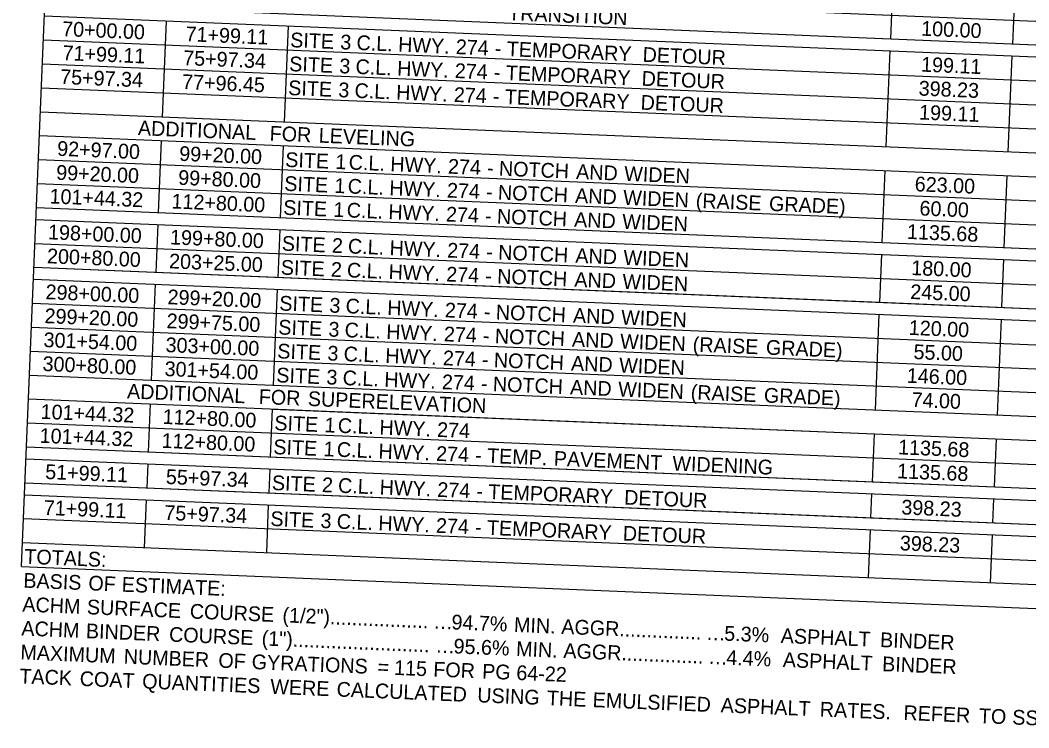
# Model space of a CAD drawing. Extents: x 1164179 to 1171425, y 1655958 to 1657208.
# Drawn here: x 1168003.6 to 1168414.3, y 1656231.5 to 1656519.5 of the extents above; entities that cross this region are included whole.
import ezdxf

# ---------------------------------------------------------------- set-up
doc = ezdxf.new("R2010")
doc.units = 0
doc.layers.add('Default', color=7, linetype='Continuous')

msp = doc.modelspace()

# ---------------------------------------------------------------- linework, layer by layer
at = {"layer": 'Default'}
for p, q in [((1168004.21, 1656297.14), (1168026.37, 1656832.93)), ((1168004.21, 1656297.14), (1168026.37, 1656832.93)), ((1168358.05, 1656511.82), (1168360.87, 1656580.01)), ((1168358.05, 1656511.82), (1168360.87, 1656580.01)), ((1168407.73, 1656509.76), (1168410.55, 1656577.96)), ((1168407.73, 1656509.76), (1168410.55, 1656577.96)), ((1168014.08, 1656535.81), (1169501.15, 1656474.29)), ((1168013.68, 1656526.07), (1168358.05, 1656511.82)), ((1168013.68, 1656526.07), (1169500.75, 1656464.55)), ((1168013.48, 1656521.19), (1169500.54, 1656459.68)), ((1168061.55, 1656480.17), (1168063.16, 1656519.14)), ((1168061.55, 1656480.17), (1168063.16, 1656519.14)), ((1168111.23, 1656478.12), (1168112.84, 1656517.08)), ((1168111.23, 1656478.12), (1168112.84, 1656517.08)), ((1168013.08, 1656511.45), (1169500.14, 1656449.94)), ((1168358.05, 1656511.82), (1169500.75, 1656464.55)), ((1168356.23, 1656467.98), (1168357.85, 1656506.95)), ((1168356.23, 1656467.98), (1168357.85, 1656506.95)), ((1168405.92, 1656465.93), (1168407.53, 1656504.89)), ((1168405.92, 1656465.93), (1168407.53, 1656504.89)), ((1168012.67, 1656501.71), (1169499.74, 1656440.19)), ((1168012.27, 1656491.97), (1169499.33, 1656430.45)), ((1168011.87, 1656482.23), (1168554.96, 1656459.76)), ((1168011.87, 1656482.23), (1169498.93, 1656420.71)), ((1168011.46, 1656472.49), (1169498.53, 1656410.97)), ((1168059.94, 1656441.21), (1168061.15, 1656470.43)), ((1168059.94, 1656441.21), (1168061.15, 1656470.43)), ((1168109.62, 1656439.15), (1168110.83, 1656468.38)), ((1168109.62, 1656439.15), (1168110.83, 1656468.38)), ((1168011.06, 1656462.74), (1169498.13, 1656401.23)), ((1168354.62, 1656429.02), (1168355.83, 1656458.24)), ((1168354.62, 1656429.02), (1168355.83, 1656458.24)), ((1168404.3, 1656426.96), (1168405.51, 1656456.18)), ((1168404.3, 1656426.96), (1168405.51, 1656456.18)), ((1168010.66, 1656453), (1169497.72, 1656391.49)), ((1168010.25, 1656443.26), (1168354.62, 1656429.02)), ((1168010.25, 1656443.26), (1169497.32, 1656381.74)), ((1168010.05, 1656438.39), (1169497.12, 1656376.87)), ((1168058.93, 1656416.85), (1168059.74, 1656436.33)), ((1168058.93, 1656416.85), (1168059.74, 1656436.33)), ((1168108.61, 1656414.8), (1168109.42, 1656434.28)), ((1168108.61, 1656414.8), (1168109.42, 1656434.28)), ((1168009.65, 1656428.65), (1169496.72, 1656367.13)), ((1168354.62, 1656429.02), (1169497.32, 1656381.74)), ((1168353.61, 1656404.66), (1168354.42, 1656424.14)), ((1168353.61, 1656404.66), (1168354.42, 1656424.14)), ((1168009.25, 1656418.91), (1168353.61, 1656404.66)), ((1168009.25, 1656418.91), (1169496.31, 1656357.39)), ((1168403.3, 1656402.61), (1168404.1, 1656422.09)), ((1168403.3, 1656402.61), (1168404.1, 1656422.09)), ((1168009.05, 1656414.04), (1169496.11, 1656352.52)), ((1168057.12, 1656373.01), (1168058.73, 1656411.98)), ((1168057.12, 1656373.01), (1168058.73, 1656411.98)), ((1168106.8, 1656370.96), (1168108.41, 1656409.93)), ((1168106.8, 1656370.96), (1168108.41, 1656409.93)), ((1168008.64, 1656404.29), (1169495.71, 1656342.78)), ((1168353.61, 1656404.66), (1169496.31, 1656357.39)), ((1168351.8, 1656360.82), (1168353.41, 1656399.79)), ((1168351.8, 1656360.82), (1168353.41, 1656399.79)), ((1168008.24, 1656394.55), (1169495.3, 1656333.04)), ((1168401.48, 1656358.77), (1168403.1, 1656397.73)), ((1168401.48, 1656358.77), (1168403.1, 1656397.73)), ((1168007.84, 1656384.81), (1169494.9, 1656323.29)), ((1168007.43, 1656375.07), (1169494.5, 1656313.55)), ((1168007.43, 1656375.07), (1169494.5, 1656313.55)), ((1168007.03, 1656365.33), (1169494.1, 1656303.81)), ((1168055.91, 1656343.79), (1168056.71, 1656363.27)), ((1168055.91, 1656343.79), (1168056.71, 1656363.27)), ((1168105.59, 1656341.73), (1168106.4, 1656361.22)), ((1168105.59, 1656341.73), (1168106.4, 1656361.22)), ((1168106.4, 1656361.22), (1168351.4, 1656351.08)), ((1168006.63, 1656355.59), (1169493.69, 1656294.07)), ((1168350.59, 1656331.6), (1168351.4, 1656351.08)), ((1168350.59, 1656331.6), (1168351.4, 1656351.08)), ((1168400.27, 1656329.54), (1168401.08, 1656349.03)), ((1168400.27, 1656329.54), (1168401.08, 1656349.03)), ((1168006.22, 1656345.84), (1168350.59, 1656331.6)), ((1168006.22, 1656345.84), (1169493.29, 1656284.33)), ((1168006.02, 1656340.97), (1169493.09, 1656279.46)), ((1168055.3, 1656329.18), (1168055.71, 1656338.92)), ((1168055.3, 1656329.18), (1168055.71, 1656338.92)), ((1168104.98, 1656327.12), (1168105.39, 1656336.86)), ((1168104.98, 1656327.12), (1168105.39, 1656336.86)), ((1168005.62, 1656331.23), (1168349.99, 1656316.99)), ((1168005.62, 1656331.23), (1169492.69, 1656269.71)), ((1168350.59, 1656331.6), (1169493.29, 1656284.33)), ((1168005.42, 1656326.36), (1169492.48, 1656264.84)), ((1168054.29, 1656304.82), (1168055.1, 1656324.31)), ((1168054.29, 1656304.82), (1168055.1, 1656324.31)), ((1168349.99, 1656316.99), (1168350.39, 1656326.73)), ((1168349.99, 1656316.99), (1168350.39, 1656326.73)), ((1168399.67, 1656314.93), (1168400.07, 1656324.67)), ((1168399.67, 1656314.93), (1168400.07, 1656324.67)), ((1168103.98, 1656302.77), (1168104.78, 1656322.25)), ((1168103.98, 1656302.77), (1168104.78, 1656322.25)), ((1168005.02, 1656316.62), (1169492.08, 1656255.1)), ((1168349.99, 1656316.99), (1169492.69, 1656269.71)), ((1168348.98, 1656292.63), (1168349.79, 1656312.12)), ((1168348.98, 1656292.63), (1168349.79, 1656312.12)), ((1168398.66, 1656290.58), (1168399.47, 1656310.06)), ((1168398.66, 1656290.58), (1168399.47, 1656310.06)), ((1168004.61, 1656306.88), (1169491.68, 1656245.36)), ((1168004.21, 1656297.14), (1169491.27, 1656235.62))]:
    msp.add_line(p, q, dxfattribs=at)

# ---------------------------------------------------------------- texts
for s, p in [(' TRANSITION', (1168200, 1656519.56)), ('70+00.00', (1168020.62, 1656513.02)), ('71+99.11', (1168070.87, 1656510.94)), ('100.00', (1168370.36, 1656513.19)), ('SITE', (1168113.46, 1656508.5)), (' 3', (1168131.64, 1656507.75)), (' C.L.', (1168138.24, 1656507.48)), ('71+99.11', (1168020.79, 1656503.25)), (' HWY.', (1168155.19, 1656506.77)), (' 274', (1168178.65, 1656505.8)), (' TEMPORARY', (1168199.39, 1656504.95)), ('75+97.34', (1168069.9, 1656501.22)), ('SITE', (1168113.06, 1656498.76)), (' -', (1168194.54, 1656505.15)), (' DETOUR', (1168254.72, 1656502.66)), (' 3', (1168131.23, 1656498.01)), (' C.L.', (1168137.84, 1656497.73)), (' HWY.', (1168154.79, 1656497.03)), (' 274', (1168178.25, 1656496.06)), (' TEMPORARY', (1168198.99, 1656495.2)), ('199.11', (1168370.33, 1656498.55)), ('75+97.34', (1168019.82, 1656493.53)), ('77+96.45', (1168069.46, 1656491.48)), (' -', (1168194.14, 1656495.41)), (' DETOUR', (1168254.32, 1656492.92)), ('SITE', (1168112.66, 1656489.02)), (' 3', (1168130.83, 1656488.27)), (' C.L.', (1168137.43, 1656487.99)), (' HWY.', (1168154.38, 1656487.29)), (' 274', (1168177.85, 1656486.32)), ('398.23', (1168369.35, 1656488.83)), (' -', (1168193.73, 1656485.66)), (' TEMPORARY', (1168198.59, 1656485.46)), (' DETOUR', (1168253.91, 1656483.17)), ('199.11', (1168369.52, 1656479.07)), ('ADDITIONAL', (1168051.48, 1656472.71)), (' FOR', (1168102.88, 1656470.58)), (' LEVELING', (1168122.85, 1656469.75)), ('92+97.00', (1168018.6, 1656464.31)), ('99+20.00', (1168068.29, 1656462.25)), ('SITE', (1168111.45, 1656459.79)), (' 1', (1168129.62, 1656459.04)), (' C.L.', (1168135.06, 1656458.82)), (' HWY.', (1168152.01, 1656458.11)), ('99+20.00', (1168018.2, 1656454.57)), (' 274', (1168175.48, 1656457.14)), (' NOTCH', (1168196.22, 1656456.29)), (' AND', (1168227.65, 1656454.99)), (' WIDEN', (1168247.22, 1656454.18)), ('99+80.00', (1168067.88, 1656452.51)), ('SITE', (1168111.05, 1656450.05)), (' -', (1168191.37, 1656456.49)), ('623.00', (1168367.74, 1656449.87)), (' 1', (1168129.22, 1656449.3)), (' C.L.', (1168134.66, 1656449.07)), (' HWY.', (1168151.61, 1656448.37)), (' 274', (1168175.07, 1656447.4)), (' NOTCH', (1168195.81, 1656446.54)), ('101+44.32', (1168015.49, 1656444.92)), ('112+80.00', (1168065.15, 1656442.87)), (' -', (1168190.96, 1656446.74)), (' AND', (1168227.25, 1656445.24)), (' WIDEN', (1168246.81, 1656444.43)), (' (RAISE', (1168276.37, 1656443.21)), (' GRADE)', (1168306.18, 1656441.98)), ('SITE', (1168110.64, 1656440.31)), (' 1', (1168128.81, 1656439.56)), (' C.L.', (1168134.26, 1656439.33)), (' HWY.', (1168151.21, 1656438.63)), (' 274', (1168174.67, 1656437.66)), ('60.00', (1168369.67, 1656440.03)), (' -', (1168190.56, 1656437)), (' NOTCH', (1168195.41, 1656436.8)), (' AND', (1168226.84, 1656435.5)), (' WIDEN', (1168246.41, 1656434.69)), ('198+00.00', (1168014.87, 1656430.31)), ('1135.68', (1168364.59, 1656430.48)), ('199+80.00', (1168064.55, 1656428.25)), ('SITE', (1168110.04, 1656425.7)), (' 2', (1168128.21, 1656424.94)), ('200+80.00', (1168014.46, 1656420.57)), (' C.L.', (1168134.75, 1656424.67)), (' HWY.', (1168151.7, 1656423.97)), (' 274', (1168175.16, 1656423)), (' NOTCH', (1168195.9, 1656422.14)), (' AND', (1168227.34, 1656420.84)), ('203+25.00', (1168064.15, 1656418.51)), (' -', (1168191.05, 1656422.35)), (' WIDEN', (1168246.9, 1656420.03)), ('SITE', (1168109.64, 1656415.95)), (' 2', (1168127.81, 1656415.2)), (' C.L.', (1168134.35, 1656414.93)), (' HWY.', (1168151.3, 1656414.23)), (' 274', (1168174.76, 1656413.26)), ('180.00', (1168366.33, 1656415.77)), (' -', (1168190.65, 1656412.6)), (' NOTCH', (1168195.5, 1656412.4)), (' AND', (1168226.93, 1656411.1)), (' WIDEN', (1168246.5, 1656410.29)), ('298+00.00', (1168013.86, 1656405.96)), ('245.00', (1168365.93, 1656406.03)), ('299+20.00', (1168063.54, 1656403.9)), ('SITE', (1168109.03, 1656401.34)), (' 3', (1168127.2, 1656400.59)), (' C.L.', (1168133.81, 1656400.32)), ('299+20.00', (1168013.46, 1656396.21)), (' HWY.', (1168150.76, 1656399.62)), (' 274', (1168174.22, 1656398.65)), (' NOTCH', (1168194.96, 1656397.79)), (' AND', (1168226.39, 1656396.49)), ('299+75.00', (1168063.14, 1656394.16)), (' -', (1168190.11, 1656397.99)), (' WIDEN', (1168245.96, 1656395.68)), ('SITE', (1168108.63, 1656391.6)), (' 3', (1168126.8, 1656390.85)), (' C.L.', (1168133.4, 1656390.58)), (' HWY.', (1168150.35, 1656389.87)), (' 274', (1168173.82, 1656388.9)), (' NOTCH', (1168194.56, 1656388.05)), ('120.00', (1168365.33, 1656391.42)), ('301+54.00', (1168013.05, 1656386.47)), ('303+00.00', (1168062.73, 1656384.42)), (' -', (1168189.7, 1656388.25)), (' AND', (1168225.99, 1656386.75)), (' WIDEN', (1168245.55, 1656385.94)), (' (RAISE', (1168275.11, 1656384.71)), ('SITE', (1168108.22, 1656381.86)), (' 3', (1168126.4, 1656381.11)), (' C.L.', (1168133, 1656380.83)), (' HWY.', (1168149.95, 1656380.13)), (' GRADE)', (1168304.92, 1656383.48)), ('55.00', (1168367.25, 1656381.58)), ('300+80.00', (1168012.65, 1656376.73)), (' 274', (1168173.41, 1656379.16)), (' NOTCH', (1168194.15, 1656378.3)), (' AND', (1168225.59, 1656377)), (' WIDEN', (1168245.15, 1656376.19)), ('301+54.00', (1168062.33, 1656374.67)), ('SITE', (1168107.82, 1656372.12)), (' 3', (1168125.99, 1656371.37)), (' -', (1168189.3, 1656378.51)), ('146.00', (1168364.52, 1656371.93)), (' C.L.', (1168132.6, 1656371.09)), (' HWY.', (1168149.55, 1656370.39)), (' 274', (1168173.01, 1656369.42)), (' NOTCH', (1168193.75, 1656368.56)), ('ADDITIONAL', (1168047.05, 1656365.55)), (' FOR', (1168098.45, 1656363.42)), (' -', (1168188.9, 1656368.76)), (' AND', (1168225.18, 1656367.26)), (' WIDEN', (1168244.75, 1656366.45)), (' (RAISE', (1168274.31, 1656365.23)), (' GRADE)', (1168304.11, 1656364)), (' SUPERELEVATION', (1168118.42, 1656362.6)), ('74.00', (1168366.45, 1656362.09)), ('101+44.32', (1168011.86, 1656357.25)), ('112+80.00', (1168061.53, 1656355.19)), ('SITE', (1168107.02, 1656352.63)), (' 1', (1168125.19, 1656351.88)), (' C.L.', (1168130.63, 1656351.66)), (' HWY.', (1168147.58, 1656350.96)), ('101+44.32', (1168011.46, 1656347.5)), (' 274', (1168171.04, 1656349.99)), ('112+80.00', (1168061.12, 1656345.45)), ('SITE', (1168106.61, 1656342.89)), ('1135.68', (1168360.97, 1656342.8)), (' 1', (1168124.78, 1656342.14)), (' C.L.', (1168130.23, 1656341.92)), (' HWY.', (1168147.18, 1656341.21)), (' 274', (1168170.64, 1656340.24)), (' TEMP.', (1168191.38, 1656339.39)), (' -', (1168186.53, 1656339.59)), (' PAVEMENT', (1168218.57, 1656338.26)), (' WIDENING', (1168266.82, 1656336.27)), ('51+99.11', (1168013.73, 1656332.77)), ('55+97.34', (1168062.85, 1656330.74)), ('1135.68', (1168360.56, 1656333.06)), ('SITE', (1168106.01, 1656328.28)), (' 2', (1168124.18, 1656327.53)), (' C.L.', (1168130.72, 1656327.26)), (' HWY.', (1168147.67, 1656326.56)), (' 274', (1168171.13, 1656325.59)), (' TEMPORARY', (1168191.87, 1656324.73)), (' DETOUR', (1168247.2, 1656322.44)), ('71+99.11', (1168013.13, 1656318.16)), (' -', (1168187.02, 1656324.93)), ('398.23', (1168362.29, 1656318.35)), ('75+97.34', (1168062.24, 1656316.13)), ('SITE', (1168105.4, 1656313.67)), (' 3', (1168123.58, 1656312.92)), (' C.L.', (1168130.18, 1656312.64)), (' HWY.', (1168147.13, 1656311.94)), (' 274', (1168170.59, 1656310.97)), (' TEMPORARY', (1168191.33, 1656310.11)), (' -', (1168186.48, 1656310.31)), (' DETOUR', (1168246.66, 1656307.82)), ('398.23', (1168361.69, 1656303.74)), ('TOTALS:', (1168005.23, 1656298.29)), ('BASIS', (1168004.83, 1656288.55)), (' OF', (1168029.07, 1656287.55)), (' ESTIMATE:', (1168042.65, 1656286.99)), ('ACHM', (1168004.43, 1656278.81)), (' SURFACE', (1168028.46, 1656277.82)), (' COURSE', (1168070.37, 1656276.08)), (' (1/2")..................', (1168108.09, 1656274.52)), ('ACHM', (1168004.02, 1656269.07)), ('94.7%', (1168179.13, 1656271.58)), (' MIN.', (1168202.35, 1656270.62)), (' AGGR...............', (1168221.62, 1656269.83)), (' BINDER', (1168028.06, 1656268.08)), (' COURSE', (1168061.92, 1656266.67)), (' (1").........................', (1168099.64, 1656265.11)), ('…', (1168171.74, 1656271.89)), ('5.3%', (1168290.17, 1656266.99)), ('  ASPHALT', (1168308.73, 1656266.22)), ('95.6%', (1168179.98, 1656261.79)), (' MIN.', (1168203.2, 1656260.83)), ('…', (1168282.77, 1656267.3)), (' BINDER', (1168351.39, 1656264.46)), ('MAXIMUM', (1168003.62, 1656259.33)), (' NUMBER', (1168043.47, 1656257.68)), ('…', (1168172.58, 1656262.1)), (' AGGR...............', (1168222.47, 1656260.03)), ('4.4%', (1168291.01, 1656257.2)), (' OF', (1168081.99, 1656256.09)), (' GYRATIONS', (1168095.56, 1656255.52)), (' 115', (1168153.54, 1656253.13)), (' FOR', (1168169.5, 1656252.47)), ('…', (1168283.62, 1656257.5)), ('  ASPHALT', (1168309.58, 1656256.43)), (' BINDER', (1168352.24, 1656254.66)), ('TACK', (1168003.22, 1656249.59)), (' COAT', (1168025.54, 1656248.66)), (' =', (1168146.79, 1656253.41)), (' PG', (1168189.39, 1656251.64)), (' 64-22', (1168203.3, 1656251.07)), (' QUANTITIES', (1168050.97, 1656247.61)), (' WERE', (1168103.12, 1656245.45)), (' CALCULATED', (1168130.13, 1656244.34)), (' USING', (1168187.4, 1656241.97)), (' THE', (1168215.73, 1656240.79)), (' EMULSIFIED', (1168234.37, 1656240.02)), (' ASPHALT', (1168286.51, 1656237.87)), (' RATES.', (1168326.85, 1656236.2)), ('  REFER', (1168358.7, 1656234.88)), (' TO', (1168391.63, 1656233.52)), (' SS-400-1', (1168405.21, 1656232.96))]:
    msp.add_text(s, height=6, rotation=357.6311, dxfattribs=at).set_placement(p)

doc.saveas('drawing.dxf')
